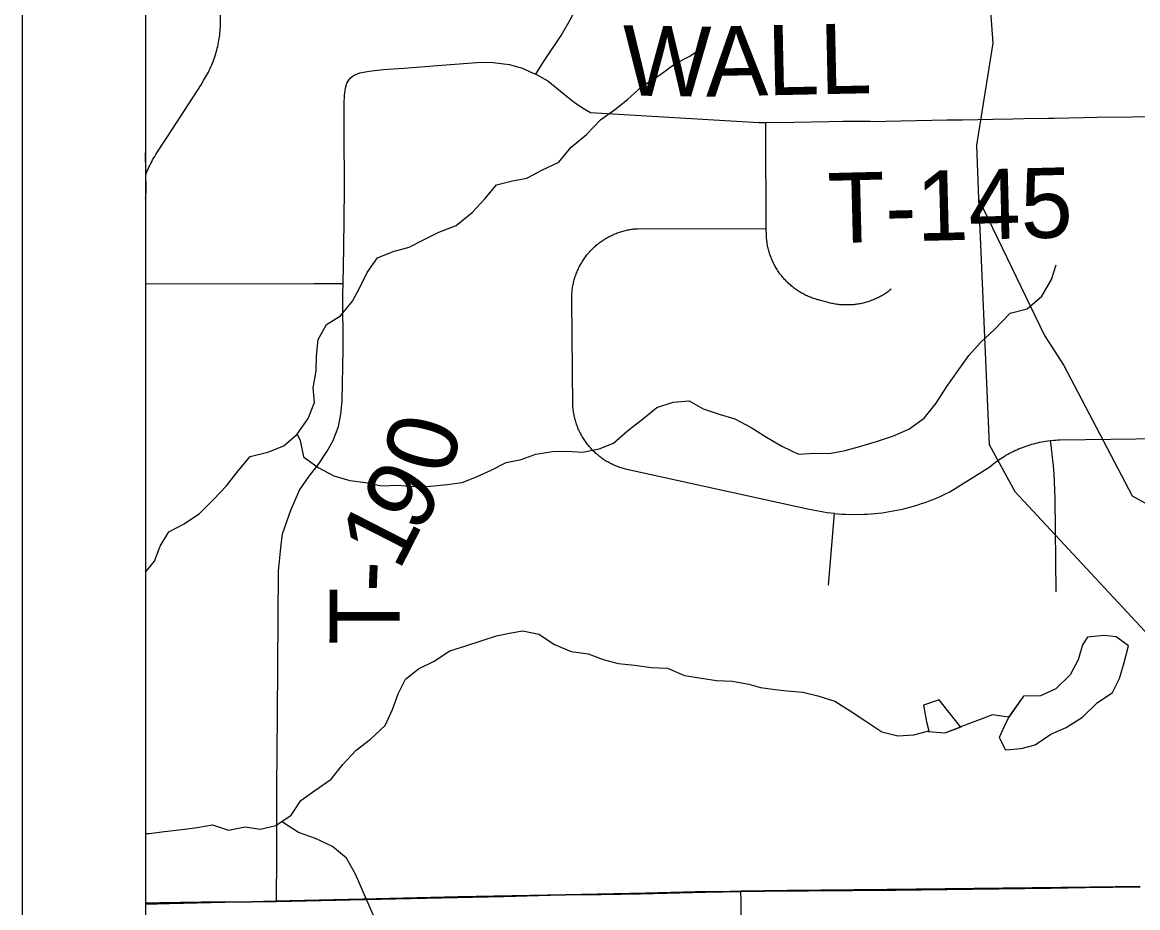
# Model space of a CAD drawing. Extents: x 0 to 34, y -5 to 22.
# Drawn here: x 2 to 2.904, y 16.518 to 17.236 of the extents above; entities that cross this region are included whole.
import ezdxf

# ---------------------------------------------------------------- set-up
doc = ezdxf.new("R2010")
doc.units = 0
for name, color, linetype in [('GM_X_County_Road', 7, 'Continuous'), ('GM_X_Minor_Lake', 7, 'Continuous'), ('GM_X_Minor_River', 7, 'Continuous'), ('GM_X_Rail_Line', 7, 'Continuous'), ('GM_X_Township_Road', 7, 'Continuous'), ('GM_X_Township_Road_Text', 7, 'Continuous'), ('GM_X_US_Route', 7, 'Continuous'), ('SH_Cut_Line', 7, 'Continuous'), ('SH_Data', 7, 'Continuous')]:
    doc.layers.add(name, color=color, linetype=linetype)

msp = doc.modelspace()

# ---------------------------------------------------------------- linework, layer by layer
at = {"layer": 'GM_X_County_Road'}
for points in [[(2.58271, 16.53151), (2.60186, 16.53171), (2.70863, 16.5327), (2.77052, 16.5335), (2.83413, 16.53432), (2.86214, 16.53472), (2.90655, 16.5353)], [(2.20601, 16.52345), (2.26591, 16.52463), (2.3152, 16.52597), (2.39034, 16.52756), (2.43784, 16.52868), (2.4693, 16.52896), (2.50138, 16.52963), (2.55384, 16.53092), (2.58271, 16.53151)], [(2.1, 16.52138), (2.11922, 16.52184), (2.16453, 16.52275), (2.20601, 16.52345)]]:
    msp.add_lwpolyline(points, dxfattribs=at)
at = {"layer": 'GM_X_Minor_Lake'}
for points in [[(2.7999, 16.67267), (2.79766, 16.66885), (2.79209, 16.65624), (2.79714, 16.6464), (2.81005, 16.6473), (2.82142, 16.65045), (2.83387, 16.65895), (2.84636, 16.6644), (2.85957, 16.6729), (2.87161, 16.68443), (2.88406, 16.69292), (2.88965, 16.70401), (2.89332, 16.71697), (2.89697, 16.7307), (2.88702, 16.73783), (2.87712, 16.73887), (2.86384, 16.73759)], [(2.86384, 16.73759), (2.85972, 16.73147), (2.85605, 16.71926), (2.84971, 16.70703), (2.83805, 16.69588), (2.82557, 16.69005), (2.81189, 16.68991), (2.79976, 16.67271)], [(2.86384, 16.73759), (2.85972, 16.73147), (2.85605, 16.71926), (2.84971, 16.70703), (2.83805, 16.69588), (2.82557, 16.69005), (2.81189, 16.68991), (2.7999, 16.67267)], [(2.76075, 16.66487), (2.74351, 16.68694), (2.73063, 16.68262), (2.73305, 16.66896), (2.73506, 16.66179)], [(2.76062, 16.66505), (2.74351, 16.68694), (2.73063, 16.68262), (2.73305, 16.66896), (2.73508, 16.66174)], [(2.73503, 16.66175), (2.73441, 16.66108), (2.74835, 16.65998), (2.76122, 16.66506)], [(2.73506, 16.66179), (2.73441, 16.66108), (2.74835, 16.65998), (2.76075, 16.66487)]]:
    msp.add_lwpolyline(points, dxfattribs=at)
at = {"layer": 'GM_X_Minor_River'}
for points in [[(2.1, 16.79025), (2.10727, 16.79917), (2.11171, 16.81138), (2.11881, 16.82286), (2.13128, 16.82946), (2.14374, 16.83795), (2.15502, 16.84909), (2.16555, 16.86023), (2.17492, 16.87249), (2.18468, 16.884), (2.19909, 16.88757), (2.21196, 16.89264), (2.22288, 16.90226), (2.23187, 16.9149), (2.23705, 16.92789), (2.23579, 16.93966), (2.23831, 16.95338), (2.23856, 16.96555), (2.23994, 16.97888), (2.24666, 16.99111), (2.25799, 16.99807), (2.26775, 17.00996), (2.27409, 17.02144), (2.27966, 17.03328), (2.2879, 17.04515), (2.30077, 17.05023), (2.31366, 17.05378), (2.32538, 17.0596), (2.33786, 17.06582), (2.35186, 17.07128), (2.36467, 17.08168), (2.3752, 17.0932), (2.38458, 17.10432), (2.39747, 17.10749), (2.40923, 17.10951), (2.4217, 17.11649), (2.43494, 17.1227), (2.44508, 17.1346), (2.45751, 17.14499), (2.46879, 17.15689), (2.48011, 17.165), (2.49066, 17.17347), (2.50271, 17.18424), (2.51668, 17.19313), (2.52912, 17.20238), (2.54122, 17.20859), (2.55405, 17.21708)], [(2.22288, 16.90226), (2.22521, 16.89696), (2.22801, 16.88367), (2.23988, 16.87505), (2.2525, 16.86833), (2.26545, 16.86466), (2.2784, 16.86289), (2.29134, 16.86035), (2.30426, 16.86087), (2.31719, 16.85986), (2.33087, 16.86), (2.34454, 16.86128), (2.35669, 16.86292), (2.36842, 16.8676), (2.38014, 16.87304), (2.39224, 16.87925), (2.40438, 16.88166), (2.4165, 16.88596), (2.42978, 16.888), (2.44155, 16.8885), (2.45448, 16.88749), (2.46776, 16.89028), (2.47949, 16.89496), (2.49079, 16.90497), (2.50285, 16.91421), (2.51454, 16.92384), (2.52779, 16.92816), (2.5407, 16.92905), (2.55217, 16.9227), (2.56514, 16.91827), (2.57772, 16.91459), (2.5911, 16.9075), (2.60334, 16.89964), (2.61595, 16.89254), (2.62933, 16.88583), (2.64224, 16.88672), (2.6544, 16.88646), (2.6673, 16.88887), (2.6798, 16.89242), (2.69344, 16.89637), (2.70632, 16.90068), (2.71881, 16.90613), (2.73126, 16.915), (2.74101, 16.92727), (2.74961, 16.94067), (2.75898, 16.95369), (2.76759, 16.96595), (2.77699, 16.97631), (2.78828, 16.98708), (2.80106, 17.00014), (2.81471, 17.0037), (2.82676, 17.01409), (2.8346, 17.02748), (2.83828, 17.03931)], [(2.1, 16.57844), (2.10273, 16.57854), (2.11525, 16.58019), (2.1293, 16.58185), (2.14182, 16.5835), (2.15434, 16.58553), (2.16731, 16.58109), (2.18058, 16.58389), (2.19276, 16.58211), (2.20565, 16.5849), (2.21811, 16.5934), (2.22597, 16.60526), (2.23728, 16.61337), (2.25049, 16.62263), (2.25987, 16.63451), (2.27077, 16.64603), (2.28246, 16.6549), (2.29412, 16.66604), (2.30007, 16.67903), (2.30488, 16.69163), (2.31084, 16.70348), (2.32139, 16.71196), (2.33387, 16.71817), (2.3467, 16.72666), (2.35958, 16.7306), (2.37284, 16.73492), (2.38458, 16.73884), (2.39633, 16.74124), (2.40582, 16.74285), (2.41877, 16.73994), (2.4314, 16.7317), (2.44514, 16.72614), (2.45884, 16.72399), (2.47105, 16.71955), (2.48325, 16.71625), (2.49656, 16.71487), (2.50988, 16.7131), (2.52319, 16.71247), (2.53694, 16.70653), (2.55064, 16.70438), (2.56282, 16.70261), (2.57575, 16.70197), (2.58908, 16.69945), (2.5986, 16.69688), (2.6104, 16.6951), (2.61992, 16.69406), (2.63285, 16.69304), (2.64504, 16.69013), (2.65877, 16.6857), (2.67139, 16.67784), (2.68402, 16.6696), (2.69703, 16.66099), (2.70999, 16.65769), (2.7229, 16.65858), (2.73503, 16.66175)], [(2.7999, 16.67267), (2.78658, 16.67482), (2.76028, 16.66472)], [(2.28557, 16.51024), (2.27029, 16.54562), (2.26294, 16.55848), (2.25144, 16.56787), (2.23769, 16.57458), (2.22395, 16.57938), (2.21095, 16.58762)]]:
    msp.add_lwpolyline(points, dxfattribs=at)
at = {"layer": 'GM_X_Rail_Line'}
for points in [[(2.87145, 18.0583), (2.84238, 18.0452), (2.8166, 18.02834), (2.7928, 18.00652), (2.7819, 17.98768), (2.77297, 17.95792), (2.76702, 17.76551), (2.77496, 17.38168), (2.77892, 17.32911), (2.78686, 17.21902), (2.7736, 17.13639), (2.77545, 17.09293)], [(2.77545, 17.09293), (2.78392, 16.89378), (2.80468, 16.85565), (3.09205, 16.5471), (3.10832, 16.53125)], [(2.77545, 17.09293), (2.82897, 16.98214), (2.84455, 16.95788), (2.89993, 16.85215), (2.94668, 16.82615), (3.01594, 16.80879), (3.06443, 16.82264), (3.43678, 16.92131), (3.48873, 16.9005), (3.58222, 16.84503), (3.59607, 16.81383), (3.60124, 16.75837)]]:
    msp.add_lwpolyline(points, dxfattribs=at)
at = {"layer": 'GM_X_Township_Road'}
msp.add_line((2.65369, 16.77974), (2.65865, 16.83783), dxfattribs=at)
for points in [[(2.41637, 17.19386), (2.42254, 17.20396), (2.43697, 17.22536), (2.44522, 17.23972), (2.45197, 17.25393), (2.45374, 17.25884), (2.45502, 17.26324), (2.45673, 17.2695), (2.45779, 17.27427), (2.45907, 17.28059), (2.45965, 17.28613), (2.46035, 17.29182), (2.46078, 17.29808), (2.46107, 17.30327), (2.46035, 17.31691), (2.45901, 17.32637), (2.45694, 17.34044), (2.45566, 17.34918), (2.45481, 17.35729), (2.45431, 17.36397), (2.4546, 17.37065), (2.45538, 17.37584), (2.4573, 17.38494)], [(2.1, 17.1121), (2.10011, 17.11239), (2.10072, 17.11393), (2.10134, 17.11546), (2.102, 17.11698), (2.10269, 17.11849), (2.1034, 17.11998), (2.10413, 17.12146), (2.1049, 17.12293), (2.10569, 17.12439), (2.1065, 17.12582), (2.10734, 17.12725), (2.1082, 17.12866), (2.10909, 17.13006), (2.12143, 17.14907), (2.1449, 17.1852), (2.14702, 17.18866), (2.14785, 17.19001), (2.14865, 17.19138), (2.14943, 17.19276), (2.15018, 17.19416), (2.15092, 17.19556), (2.15162, 17.19699), (2.1523, 17.19842), (2.15296, 17.19986), (2.15359, 17.20132), (2.15419, 17.20278), (2.15477, 17.20426), (2.15532, 17.20575), (2.15585, 17.20724), (2.15635, 17.20875), (2.15683, 17.21026), (2.15728, 17.21178), (2.1577, 17.21331), (2.15809, 17.21484), (2.15846, 17.21639), (2.1588, 17.21794), (2.15912, 17.21949), (2.15941, 17.22105), (2.15967, 17.22262), (2.1599, 17.22418), (2.1601, 17.22576), (2.16028, 17.22733), (2.16043, 17.22891), (2.16055, 17.2305), (2.16065, 17.23208), (2.16072, 17.23367), (2.15964, 17.30881)], [(2.1, 17.02414), (2.18863, 17.02399), (2.23672, 17.02416), (2.2602, 17.02425), (2.26083, 17.05284), (2.26131, 17.10075), (2.26111, 17.14859), (2.26104, 17.16998), (2.26125, 17.17681), (2.26196, 17.1825), (2.26317, 17.18655), (2.26573, 17.1906), (2.26857, 17.1928), (2.27362, 17.19494), (2.28137, 17.19636), (2.29253, 17.19763), (2.30945, 17.19884), (2.33667, 17.20098), (2.36134, 17.20275), (2.36845, 17.20325), (2.37484, 17.20368), (2.38181, 17.20346), (2.38835, 17.20261), (2.39496, 17.20168), (2.39972, 17.20041), (2.40548, 17.19866), (2.4128, 17.19526), (2.41637, 17.19386), (2.42605, 17.18838), (2.43948, 17.17769), (2.44742, 17.1713), (2.4543, 17.16668), (2.4607, 17.1628), (2.59709, 17.15466), (2.60286, 17.15476), (2.62551, 17.15512), (2.65394, 17.15557), (2.66531, 17.15575), (2.6755, 17.15591), (2.68751, 17.1557), (2.69476, 17.15558), (2.70031, 17.1557), (2.71233, 17.15598), (2.72513, 17.15627), (2.73745, 17.15655), (2.74994, 17.15678), (2.76226, 17.157), (2.77476, 17.15723), (2.78719, 17.15745), (2.80317, 17.15775), (2.81201, 17.15791), (2.83212, 17.15827), (2.83681, 17.15836), (2.86053, 17.1588), (2.87148, 17.15895), (2.89977, 17.15934), (2.92046, 17.15963)], [(2.7045, 17.01957), (2.7031, 17.01846), (2.7023, 17.01786), (2.7015, 17.01729), (2.70069, 17.01671), (2.69986, 17.01616), (2.69903, 17.01563), (2.69819, 17.0151), (2.69733, 17.01459), (2.69647, 17.0141), (2.6956, 17.01361), (2.69472, 17.01315), (2.69384, 17.0127), (2.69294, 17.01227), (2.69204, 17.01185), (2.69113, 17.01145), (2.69022, 17.01106), (2.68929, 17.01069), (2.68837, 17.01034), (2.68743, 17.01), (2.68648, 17.00968), (2.68554, 17.00937), (2.68459, 17.00908), (2.68363, 17.00881), (2.68267, 17.00856), (2.6817, 17.00831), (2.68073, 17.0081), (2.67976, 17.00789), (2.67878, 17.0077), (2.6778, 17.00753), (2.67681, 17.00737), (2.67583, 17.00724), (2.67484, 17.00712), (2.67386, 17.00701), (2.67286, 17.00693), (2.66295, 17.00703), (2.66196, 17.00714), (2.66098, 17.00726), (2.66, 17.0074), (2.65902, 17.00756), (2.65805, 17.00773), (2.65707, 17.00792), (2.6561, 17.00813), (2.65514, 17.00835), (2.65418, 17.00859), (2.65333, 17.00882), (2.64565, 17.01089), (2.6448, 17.01113), (2.64374, 17.01143), (2.6428, 17.01172), (2.64186, 17.01204), (2.64092, 17.01236), (2.64, 17.0127), (2.63907, 17.01305), (2.63816, 17.01343), (2.63725, 17.01382), (2.63635, 17.01422), (2.63546, 17.01465), (2.63457, 17.01509), (2.63368, 17.01553), (2.63281, 17.01601), (2.63195, 17.01648), (2.6311, 17.01699), (2.63025, 17.0175), (2.62942, 17.01803), (2.62859, 17.01857), (2.62777, 17.01913), (2.62696, 17.0197), (2.62617, 17.02028), (2.62538, 17.02088), (2.6246, 17.02149), (2.62383, 17.02212), (2.62308, 17.02276), (2.62233, 17.02341), (2.6216, 17.02408), (2.62088, 17.02475), (2.62016, 17.02544), (2.61947, 17.02615), (2.61878, 17.02686), (2.61811, 17.02759), (2.61745, 17.02833), (2.6168, 17.02908), (2.61617, 17.02984), (2.61555, 17.03061), (2.61494, 17.0314), (2.61434, 17.03219), (2.61376, 17.03299), (2.6132, 17.03381), (2.61265, 17.03463), (2.6121, 17.03547), (2.61158, 17.03631), (2.61107, 17.03716), (2.61058, 17.03802), (2.6101, 17.03889), (2.60964, 17.03977), (2.60919, 17.04066), (2.60876, 17.04154), (2.60834, 17.04245), (2.60794, 17.04335), (2.60755, 17.04427), (2.60718, 17.04519), (2.60682, 17.04612), (2.60649, 17.04705), (2.60616, 17.04799), (2.60586, 17.04893), (2.60557, 17.04988), (2.60529, 17.05084), (2.60504, 17.0518), (2.6048, 17.05276), (2.60457, 17.05373), (2.60437, 17.0547), (2.60418, 17.05567), (2.60401, 17.05665), (2.60385, 17.05763), (2.60371, 17.05861), (2.60359, 17.0596), (2.60349, 17.06059), (2.6034, 17.06158), (2.60332, 17.06257), (2.60314, 17.06892), (2.60288, 17.14907), (2.60286, 17.15476)], [(2.1, 17.09286), (2.10001, 17.09296), (2.10016, 17.09454), (2.10028, 17.09612), (2.10038, 17.09771), (2.10045, 17.09929), (2.1, 17.13031)], [(2.65865, 16.83783), (2.65568, 16.83815), (2.65272, 16.83851), (2.64977, 16.83893), (2.64682, 16.8394), (2.64389, 16.83992), (2.64096, 16.84049), (2.63805, 16.84112), (2.49009, 16.87363), (2.48841, 16.87403), (2.48745, 16.87428), (2.4865, 16.87456), (2.48556, 16.87484), (2.48462, 16.87515), (2.48369, 16.87548), (2.48275, 16.87582), (2.48183, 16.87617), (2.48092, 16.87655), (2.48001, 16.87694), (2.47911, 16.87735), (2.47822, 16.87777), (2.47733, 16.8782), (2.47645, 16.87866), (2.47558, 16.87913), (2.47472, 16.87962), (2.47387, 16.88011), (2.47302, 16.88063), (2.47218, 16.88116), (2.47136, 16.8817), (2.47054, 16.88226), (2.46974, 16.88283), (2.46894, 16.88342), (2.46815, 16.88403), (2.46738, 16.88464), (2.46661, 16.88527), (2.46586, 16.88591), (2.46512, 16.88657), (2.46439, 16.88723), (2.46367, 16.88792), (2.46296, 16.88861), (2.46227, 16.88931), (2.46158, 16.89003), (2.46091, 16.89076), (2.46026, 16.8915), (2.45961, 16.89225), (2.45899, 16.89302), (2.45837, 16.89379), (2.45776, 16.89458), (2.45718, 16.89537), (2.4566, 16.89618), (2.45604, 16.897), (2.45549, 16.89783), (2.45496, 16.89866), (2.45444, 16.89951), (2.45394, 16.90036), (2.45345, 16.90123), (2.45298, 16.9021), (2.45252, 16.90298), (2.45208, 16.90387), (2.45165, 16.90477), (2.45124, 16.90568), (2.45085, 16.90659), (2.45047, 16.9075), (2.45011, 16.90843), (2.44975, 16.90935), (2.44942, 16.91029), (2.44911, 16.91123), (2.44881, 16.91217), (2.44852, 16.91313), (2.44826, 16.91408), (2.44801, 16.91505), (2.44778, 16.91601), (2.44756, 16.91698), (2.44735, 16.91795), (2.44717, 16.91892), (2.447, 16.9199), (2.44685, 16.92088), (2.44671, 16.92187), (2.44659, 16.92285), (2.44649, 16.92384), (2.4464, 16.92483), (2.44547, 17.01136), (2.44564, 17.01648), (2.44573, 17.01747), (2.44583, 17.01845), (2.44596, 17.01944), (2.4461, 17.02042), (2.44625, 17.0214), (2.44643, 17.02237), (2.44662, 17.02335), (2.44683, 17.02432), (2.44705, 17.02528), (2.44729, 17.02625), (2.44755, 17.0272), (2.44783, 17.02816), (2.44812, 17.0291), (2.44842, 17.03005), (2.44875, 17.03099), (2.44909, 17.03192), (2.44945, 17.03284), (2.44982, 17.03376), (2.45021, 17.03468), (2.45061, 17.03558), (2.45103, 17.03648), (2.45147, 17.03737), (2.45192, 17.03826), (2.45239, 17.03913), (2.45287, 17.04), (2.45337, 17.04085), (2.45388, 17.04171), (2.45441, 17.04254), (2.45495, 17.04338), (2.45551, 17.0442), (2.45607, 17.04501), (2.45666, 17.04581), (2.45726, 17.0466), (2.45787, 17.04738), (2.4585, 17.04816), (2.45914, 17.04891), (2.45979, 17.04966), (2.46045, 17.0504), (2.46113, 17.05112), (2.46182, 17.05183), (2.46252, 17.05254), (2.46324, 17.05322), (2.46396, 17.0539), (2.4647, 17.05456), (2.46545, 17.05521), (2.46621, 17.05585), (2.46698, 17.05647), (2.46777, 17.05708), (2.46856, 17.05767), (2.46936, 17.05826), (2.47018, 17.05882), (2.471, 17.05938), (2.47183, 17.05992), (2.47268, 17.06044), (2.47353, 17.06095), (2.47438, 17.06145), (2.47525, 17.06193), (2.47613, 17.06239), (2.47701, 17.06284), (2.47791, 17.06327), (2.47881, 17.06369), (2.47972, 17.06409), (2.48063, 17.06448), (2.48155, 17.06485), (2.48247, 17.06521), (2.48341, 17.06554), (2.48434, 17.06586), (2.48529, 17.06617), (2.48624, 17.06646), (2.48719, 17.06673), (2.48815, 17.06698), (2.48912, 17.06723), (2.49008, 17.06744), (2.49105, 17.06765), (2.49202, 17.06784), (2.493, 17.06801), (2.49398, 17.06816), (2.49496, 17.0683), (2.49595, 17.06842), (2.49694, 17.06852), (2.49793, 17.0686), (2.49892, 17.06867), (2.60314, 17.06892)], [(2.20601, 16.52345), (2.20628, 16.56054), (2.2065, 16.61528), (2.207, 16.67501), (2.20749, 16.75304), (2.20765, 16.79104), (2.20957, 16.80995), (2.21099, 16.82146), (2.21768, 16.84051), (2.22479, 16.85672), (2.23253, 16.86823), (2.23992, 16.8774), (2.24711, 16.88835), (2.25194, 16.89688), (2.25641, 16.90847), (2.25841, 16.91828), (2.2594, 16.92908), (2.26019, 16.97074), (2.25995, 17.01577), (2.2602, 17.02425)], [(2.65865, 16.83783), (2.66162, 16.83757), (2.66459, 16.83736), (2.66757, 16.8372), (2.67055, 16.83709), (2.68247, 16.83719), (2.68544, 16.83734), (2.68841, 16.83755), (2.69139, 16.83782), (2.69435, 16.83813), (2.69731, 16.83849), (2.70026, 16.8389), (2.7032, 16.83937), (2.70614, 16.83989), (2.70906, 16.84046), (2.71198, 16.84108), (2.71488, 16.84176), (2.71777, 16.84248), (2.72065, 16.84326), (2.72352, 16.84409), (2.72637, 16.84496), (2.72921, 16.84589), (2.73203, 16.84686), (2.73484, 16.84788), (2.73763, 16.84894), (2.74041, 16.85005), (2.74317, 16.85121), (2.7459, 16.85241), (2.74861, 16.85367), (2.75208, 16.85538), (2.78447, 16.87569), (2.7868, 16.8776), (2.78809, 16.87861), (2.7894, 16.87959), (2.79073, 16.88055), (2.79208, 16.88149), (2.79344, 16.88241), (2.79482, 16.88329), (2.79621, 16.88416), (2.79762, 16.885), (2.79905, 16.88582), (2.80049, 16.88661), (2.80194, 16.88737), (2.80341, 16.8881), (2.80488, 16.88882), (2.80638, 16.8895), (2.80788, 16.89016), (2.8094, 16.89079), (2.81092, 16.89139), (2.81247, 16.89197), (2.81401, 16.89252), (2.81557, 16.89304), (2.81714, 16.89353), (2.81872, 16.894), (2.8203, 16.89444), (2.82189, 16.89485), (2.82349, 16.89523), (2.8251, 16.89558), (2.82671, 16.89591), (2.82834, 16.89621), (2.82996, 16.89647), (2.83159, 16.89672), (2.83382, 16.89699), (2.83651, 16.89726), (2.83815, 16.89738), (2.83979, 16.89747), (2.84145, 16.89754), (3.00574, 16.89977)], [(2.83822, 16.77444), (2.83746, 16.85004), (2.8373, 16.85668), (2.83701, 16.86332), (2.83661, 16.86996), (2.83608, 16.87659), (2.83545, 16.88321), (2.83459, 16.89072), (2.83382, 16.89699)], [(2.58302, 16.51141), (2.58282, 16.52382), (2.58271, 16.53151)]]:
    msp.add_lwpolyline(points, dxfattribs=at)
at = {"layer": 'GM_X_US_Route'}
for points in [[(2.1, 20.9), (2.1, 16.52208), (2.11121, 16.52239), (2.1454, 16.52285), (2.18578, 16.52321), (2.20518, 16.52365), (2.27585, 16.52521), (2.35351, 16.52726), (2.44044, 16.52894), (2.50559, 16.53023), (2.54594, 16.53119), (2.57391, 16.53154), (2.58249, 16.53166), (2.62051, 16.53222), (2.70129, 16.53304), (2.86594, 16.53499), (2.90622, 16.53565)], [(2.90622, 16.53565), (2.86594, 16.53499), (2.70129, 16.53304), (2.62051, 16.53222), (2.58249, 16.53166), (2.57391, 16.53154), (2.54594, 16.53119), (2.50559, 16.53023), (2.44044, 16.52894), (2.35351, 16.52726), (2.27585, 16.52521), (2.20518, 16.52365), (2.18578, 16.52321), (2.1454, 16.52285), (2.11121, 16.52239), (2.1, 16.52208), (2.1, 14.1)]]:
    msp.add_lwpolyline(points, dxfattribs=at)
at = {"layer": 'SH_Cut_Line'}
for points in [[(2.1, 20.9), (2.1, 16.52208), (2.11121, 16.52239), (2.1454, 16.52285), (2.18578, 16.52321), (2.20518, 16.52365), (2.27585, 16.52521), (2.35351, 16.52726), (2.44044, 16.52894), (2.50559, 16.53023), (2.54594, 16.53119), (2.57391, 16.53154), (2.58249, 16.53166), (2.62051, 16.53222), (2.70129, 16.53304), (2.86594, 16.53499), (2.90622, 16.53565)], [(2.90622, 16.53565), (2.86594, 16.53499), (2.70129, 16.53304), (2.62051, 16.53222), (2.58249, 16.53166), (2.57391, 16.53154), (2.54594, 16.53119), (2.50559, 16.53023), (2.44044, 16.52894), (2.35351, 16.52726), (2.27585, 16.52521), (2.20518, 16.52365), (2.18578, 16.52321), (2.1454, 16.52285), (2.11121, 16.52239), (2.1, 16.52208), (2.1, 14.1)]]:
    msp.add_lwpolyline(points, dxfattribs=at)
at = {"layer": 'SH_Data'}
for p, q in [((2, 21), (2, 14)), ((2.1, 20.9), (2.1, 14.1))]:
    msp.add_line(p, q, dxfattribs=at)

# ---------------------------------------------------------------- texts
at = {"layer": 'GM_X_Township_Road_Text'}
for s, height, rotation, p in [('W', 0.05682, 359.08144, (2.48625, 17.17668)), ('A', 0.05682, 1.23934, (2.55441, 17.17563)), ('L', 0.05682, 1.20867, (2.60439, 17.17671)), ('L', 0.05682, 1.20867, (2.64688, 17.17761)), ('T-145', 0.056818, 1.41013, (2.65384, 17.05689)), ('0', 0.05682, 75.51946, (2.34663, 16.8674)), ('9', 0.05682, 57.94111, (2.32058, 16.82035)), ('1', 0.05682, 62.97878, (2.30533, 16.79032)), ('-', 0.05682, 87.5952, (2.30597, 16.7732)), ('T', 0.05682, 89.87999, (2.3059, 16.7313))]:
    msp.add_text(s, height=height, rotation=rotation, dxfattribs=at).set_placement(p)

doc.saveas('drawing.dxf')
